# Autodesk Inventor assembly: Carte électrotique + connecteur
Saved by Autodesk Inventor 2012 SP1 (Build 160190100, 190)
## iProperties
Created: 2014-12
Part Number: Carte électrotique + connecteur
Document SubType Name: Assembly
Designer: Bruno
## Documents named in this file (4)
- D:\Cours\Systèmes\secateur-hydrogene-Pragma\Documentation\Dossier technique Infaco F3005\Solidworks\Composants importés\F3005\Carte électrotique + connecteur.iam
- D:\Cours\Systèmes\secateur-hydrogene-Pragma\Documentation\Dossier technique Infaco F3005\Solidworks\Composants importés\F3005\Carte électronique.ipt
- D:\Cours\Systèmes\secateur-hydrogene-Pragma\Documentation\Dossier technique Infaco F3005\Solidworks\Composants importés\F3005\Fils.ipt
- D:\Cours\Systèmes\secateur-hydrogene-Pragma\Documentation\Dossier technique Infaco F3005\Solidworks\Composants importés\F3005\Connecteur.ipt
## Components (3 placed, 3 different names)
1. Carte électronique:1
2. Fils:1
3. Connecteur:1
